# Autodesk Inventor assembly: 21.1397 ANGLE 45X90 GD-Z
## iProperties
Created: 2011-05
Part Number: 21.1397 ANGLE 45X90 GD-Z
Document SubType Name: Assembly
Designer: Administrator
Author: Administrator
